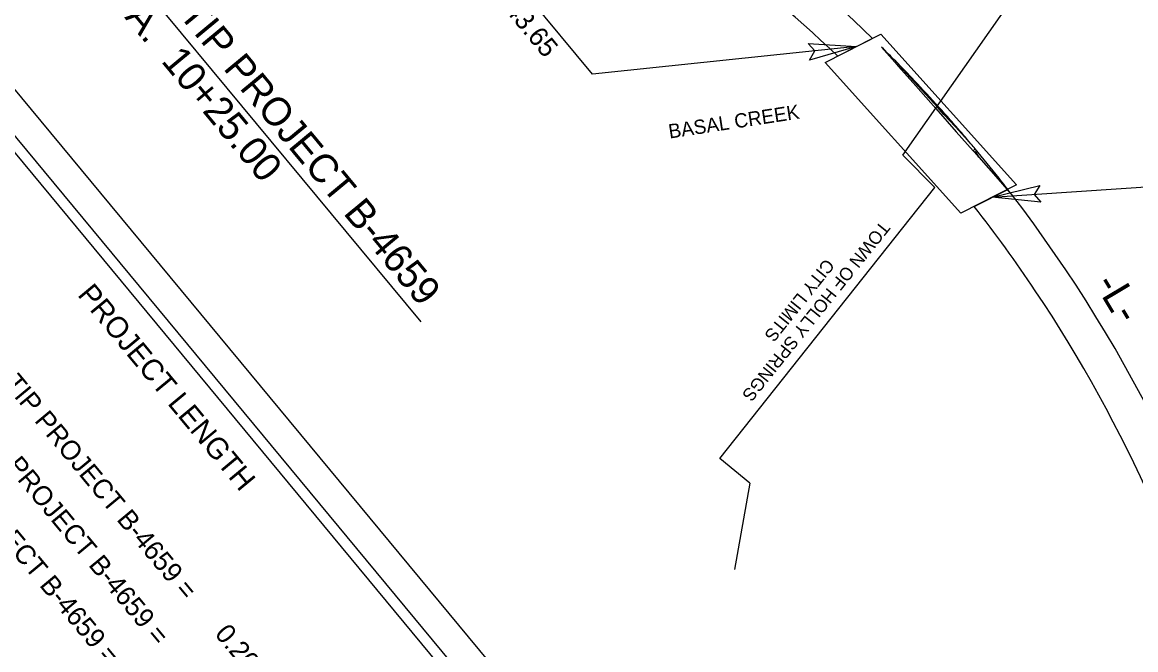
# Model space of a CAD drawing. Extents: x 2054826 to 2060231, y 685508 to 690809.
# Drawn here: x 2058198 to 2058981, y 688383 to 688824 of the extents above; entities that cross this region are included whole.
import ezdxf

# ---------------------------------------------------------------- set-up
doc = ezdxf.new("R2010")
doc.units = 0
for name, color, linetype in [('Default', 7, 'Continuous'), ('Old_Level_11', 7, 'Continuous'), ('Old_Level_21', 7, 'Continuous'), ('Prop Dimension Text', 7, 'Continuous'), ('Prop Horizontal Alignment Station Label', 7, 'Continuous'), ('Prop RDY Alternate Text Purple', 7, 'Continuous'), ('Prop Shade Heavy', 7, 'Continuous'), ('Prop Shade Medium', 7, 'Continuous'), ('Prop Terminator CELL', 7, 'Continuous'), ('Sheet Title CELL', 7, 'Continuous')]:
    doc.layers.add(name, color=color, linetype=linetype)

msp = doc.modelspace()

# ---------------------------------------------------------------- linework, layer by layer
at = {"layer": 'Default'}
for p, q in [((2058802.5, 688806.92), (2058811.77, 688796.43)), ((2058812.41, 688797), (2058811.77, 688796.43)), ((2058811.77, 688796.43), (2058812.41, 688797)), ((2058811.77, 688796.43), (2058814.5, 688793.33)), ((2058814.5, 688793.33), (2058815.04, 688793.83)), ((2058815.04, 688793.83), (2058825.08, 688782.87)), ((2058825.53, 688783.44), (2058825.08, 688782.87)), ((2058825.08, 688782.87), (2058825.53, 688783.44)), ((2058825.08, 688782.87), (2058842, 688764.4)), ((2058842, 688764.4), (2058842.79, 688764.78)), ((2058842.79, 688764.78), (2058842, 688764.4)), ((2058842, 688764.4), (2058846.34, 688759.67)), ((2058846.34, 688759.67), (2058846.79, 688760.2)), ((2058846.34, 688759.67), (2058854.48, 688750.79)), ((2058846.79, 688760.2), (2058846.8, 688760.32)), ((2058854.48, 688750.79), (2058854.88, 688751.15)), ((2058854.88, 688751.15), (2058854.48, 688750.79)), ((2058854.48, 688750.79), (2058865.36, 688738.91)), ((2058868.3, 688735.42), (2058866.85, 688734.1)), ((2058866.85, 688734.1), (2058868.3, 688735.42)), ((2058866.85, 688734.1), (2058867.8, 688733.03)), ((2058867.8, 688733.03), (2058868.44, 688733.62)), ((2058868.44, 688733.62), (2058867.8, 688733.03)), ((2058867.8, 688733.03), (2058870.81, 688729.62)), ((2058868.44, 688733.62), (2058870.81, 688729.62)), ((2058870.81, 688729.62), (2058868.44, 688733.62)), ((2058870.81, 688729.62), (2058884.5, 688714.13)), ((2058884.5, 688714.13), (2058885.14, 688714.7)), ((2058885.14, 688714.7), (2058884.5, 688714.13)), ((2058884.5, 688714.13), (2058893.77, 688703.64))]:
    msp.add_line(p, q, dxfattribs=at)
for points in [[(2058865.36, 688738.91), (2058854.48, 688750.79), (2058846.34, 688759.67), (2058842, 688764.4), (2058825.08, 688782.87), (2058815.04, 688793.83), (2058814.5, 688793.33)], [(2058814.5, 688793.33), (2058826.49, 688779.77), (2058840.61, 688763.8), (2058855.05, 688747.45), (2058866.85, 688734.1)], [(2058846.8, 688760.32), (2058846.79, 688760.2), (2058846.34, 688759.67)]]:
    msp.add_lwpolyline(points, dxfattribs=at)
for start, end in [(44.57781, 45.37193), (43.50962, 44.57781), (42.07066, 43.50962), (41.73096, 42.07066), (41.03901, 41.73096), (40.12661, 41.03901), (39.86838, 40.12661), (38.35644, 39.86838), (37.56231, 38.35644)]:
    msp.add_arc((2058091.57, 688086.7), 1012, start, end, dxfattribs=at)
at = {"layer": 'Old_Level_21'}
msp.add_lwpolyline([(2058588.27, 689338), (2059498.4, 688240.46), (2058988.43, 687817.56), (2058078.29, 688915.11)], close=True, dxfattribs=at)
at = {"layer": 'Prop Dimension Text'}
for p, q in [((2058481.13, 688930.04), (2058599, 688787.9)), ((2058784.91, 688807.31), (2058599.08, 688787.86)), ((2058880.34, 688701.38), (2058999.28, 688709.47))]:
    msp.add_line(p, q, dxfattribs=at)
at = {"layer": 'Prop Horizontal Alignment Station Label'}
msp.add_line((2058478.6, 688613.8), (2058240.57, 688900.83), dxfattribs=at)
at = {"layer": 'Prop RDY Alternate Text Purple'}
for p, q in [((2058817.56, 688730.88), (2058926.94, 688886.98)), ((2058839.84, 688708.33), (2058817.56, 688730.88)), ((2058688.61, 688517.64), (2058839.84, 688708.33)), ((2058709.88, 688500.44), (2058688.61, 688517.64)), ((2058709.88, 688500.44), (2058698.95, 688439.57))]:
    msp.add_line(p, q, dxfattribs=at)
at = {"layer": 'Prop Shade Heavy'}
for p, q in [((2058762.86, 688796.07), (2058802.06, 688816.05)), ((2058802.06, 688816.05), (2058897.49, 688710.12)), ((2058858.29, 688690.13), (2058762.86, 688796.07)), ((2058897.49, 688710.12), (2058858.29, 688690.13))]:
    msp.add_line(p, q, dxfattribs=at)
at = {"layer": 'Prop Shade Medium'}
for p, q in [((2058796.21, 688813.07), (2058771.7, 688800.57)), ((2058867.65, 688694.9), (2058891.24, 688706.93))]:
    msp.add_line(p, q, dxfattribs=at)
for radius, start, end in [(1012, 45.87384, 62.50587), (986, 46.39073, 61.45895), (1012, 37.56231, 37.80158), (1012, 13.85856, 37.56231), (986, 33.83723, 38.08957), (986, 13.85856, 33.83723)]:
    msp.add_arc((2058091.62, 688086.65), radius, start, end, dxfattribs=at)
at = {"layer": 'Prop Terminator CELL'}
for points in [[(2058750.74, 688809.57), (2058784.91, 688807.31), (2058751.78, 688797.81), (2058755.45, 688804.22)], [(2058914.41, 688697.87), (2058880.34, 688701.38), (2058913.8, 688709.67), (2058909.9, 688703.39)]]:
    msp.add_lwpolyline(points, close=True, dxfattribs=at)
at = {"layer": 'Sheet Title CELL'}
for p, q in [((2057819.13, 689194.85), (2059178.76, 687555.25)), ((2058138.88, 688797.47), (2058502.73, 688358.7))]:
    msp.add_line(p, q, dxfattribs=at)

# ---------------------------------------------------------------- texts
at = {"layer": 'Default'}
msp.add_text('BASAL CREEK', height=10, rotation=8.75304, dxfattribs=at).set_placement((2058653.39, 688742.62))
at = {"layer": 'Old_Level_11'}
for s, p in [('LENGTH ROADWAY TIP PROJECT B-4659 = ', (2058070.32, 688707.4)), ('LENGTH STRUCTURE TIP PROJECT B-4659 = ', (2058038.83, 688689.47)), ('TOTAL LENGTH TIP PROJECT B-4659 = ', (2058038.76, 688633.85)), ('0.205 MILE', (2058332.83, 688394.06))]:
    msp.add_text(s, height=13.672, rotation=309.74237, dxfattribs=at).set_placement(p)
at = {"layer": 'Prop Dimension Text'}
for s, height, rotation, p in [('-L- STA.  15+43.65', 13.5, 309.66721, (2058467.93, 688916.39)), ('TOWN OF HOLLY SPRINGS', 9, 231.30571, (2058802.13, 688685.24)), ('CITY LIMITS', 9, 231.30571, (2058763.07, 688658.8)), ('-L-', 21, 300.8634, (2058951.92, 688640.44))]:
    msp.add_text(s, height=height, rotation=rotation, dxfattribs=at).set_placement(p)
at = {"layer": 'Prop Horizontal Alignment Station Label'}
for s, p in [('BEGIN TIP PROJECT B-4659 ', (2058249.73, 688899.38)), ('-L- STA.  10+25.00  ', (2058222.17, 688884.99))]:
    msp.add_text(s, height=20, rotation=309.66721, dxfattribs=at).set_placement(p)
at = {"layer": 'Sheet Title CELL'}
msp.add_text('PROJECT LENGTH', height=14.9994, rotation=309.66721, dxfattribs=at).set_placement((2058236.37, 688632.59))

doc.saveas('drawing.dxf')
